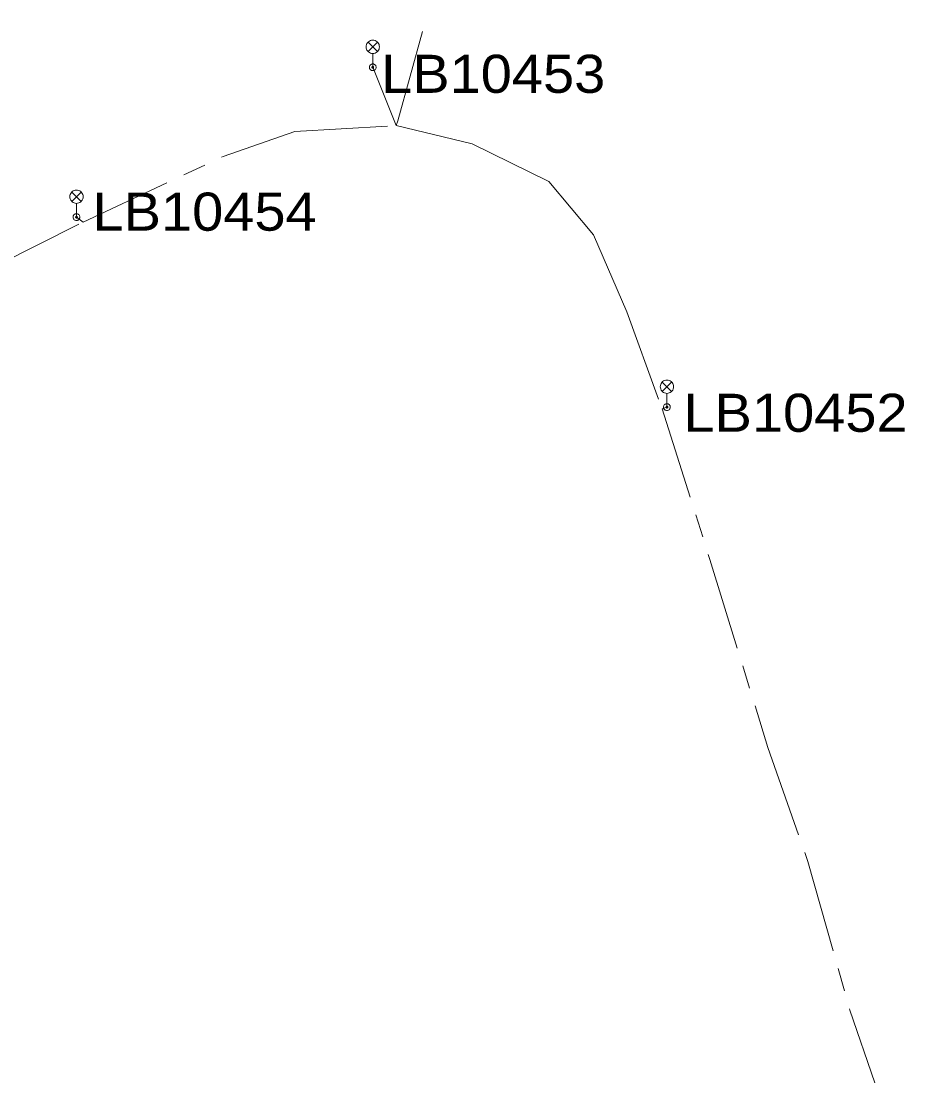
# Model space of a CAD drawing. Extents: x -691843 to -691118, y -976392 to -975793.
# Drawn here: x -691778.5 to -691728.8, y -976391.8 to -976332 of the extents above; entities that cross this region are included whole.
import ezdxf

# ---------------------------------------------------------------- set-up
doc = ezdxf.new("R2010")
doc.units = 0
doc.header["$LTSCALE"] = 0.87
doc.linetypes.add('LONG_DASH_SHORT_DASH', pattern=[9.9, 6, -1.2, 1.5, -1.2])
doc.layers.add('1', color=7, linetype='Continuous', lineweight=13)

msp = doc.modelspace()

# ---------------------------------------------------------------- linework, layer by layer
at = {"layer": '1'}
for p, q in [((-691759.005, -976333.215), (-691758.475, -976333.745)), ((-691759.005, -976333.745), (-691758.475, -976333.215)), ((-691758.74, -976334.63), (-691758.74, -976333.855)), ((-691775.695, -976341.655), (-691775.165, -976342.185)), ((-691775.695, -976342.185), (-691775.165, -976341.655)), ((-691775.43, -976343.07), (-691775.43, -976342.295)), ((-691742.435, -976352.355), (-691741.905, -976352.885)), ((-691742.435, -976352.885), (-691741.905, -976352.355)), ((-691742.17, -976353.77), (-691742.17, -976352.995))]:
    msp.add_line(p, q, dxfattribs=at)
at = {"layer": '1', "linetype": 'LONG_DASH_SHORT_DASH'}
for p, q in [((-691757.43, -976337.91), (-691758.74, -976334.63)), ((-691757.43, -976337.91), (-691758.74, -976334.63)), ((-691757.43, -976337.91), (-691758.74, -976334.63)), ((-691757.43, -976337.91), (-691758.74, -976334.63)), ((-691757.43, -976337.91), (-691758.74, -976334.63)), ((-691757.43, -976337.91), (-691758.74, -976334.63)), ((-691757.43, -976337.91), (-691758.74, -976334.63)), ((-691757.43, -976337.91), (-691758.74, -976334.63)), ((-691775.06, -976343.35), (-691775.43, -976343.07)), ((-691775.06, -976343.35), (-691775.43, -976343.07)), ((-691775.06, -976343.35), (-691775.43, -976343.07)), ((-691775.06, -976343.35), (-691775.43, -976343.07)), ((-691775.06, -976343.35), (-691775.43, -976343.07)), ((-691775.06, -976343.35), (-691775.43, -976343.07)), ((-691775.06, -976343.35), (-691775.43, -976343.07)), ((-691775.06, -976343.35), (-691775.43, -976343.07)), ((-691742.44, -976353.86), (-691742.17, -976353.77)), ((-691742.44, -976353.86), (-691742.17, -976353.77)), ((-691742.44, -976353.86), (-691742.17, -976353.77)), ((-691742.44, -976353.86), (-691742.17, -976353.77)), ((-691742.44, -976353.86), (-691742.17, -976353.77)), ((-691742.44, -976353.86), (-691742.17, -976353.77)), ((-691742.44, -976353.86), (-691742.17, -976353.77)), ((-691742.44, -976353.86), (-691742.17, -976353.77))]:
    msp.add_line(p, q, dxfattribs=at)
for points in [[(-691757.43, -976337.91), (-691757.33, -976337.64), (-691754.54, -976327.6), (-691754.53, -976324.41), (-691755.09, -976321.54), (-691752.36, -976320.81), (-691753.85, -976315.74)], [(-691757.43, -976337.91), (-691757.33, -976337.64), (-691754.54, -976327.6), (-691754.53, -976324.41), (-691755.09, -976321.54), (-691752.36, -976320.81), (-691753.85, -976315.74)], [(-691757.43, -976337.91), (-691757.33, -976337.64), (-691754.54, -976327.6), (-691754.53, -976324.41), (-691755.09, -976321.54), (-691752.36, -976320.81), (-691753.85, -976315.74)], [(-691757.43, -976337.91), (-691757.33, -976337.64), (-691754.54, -976327.6), (-691754.53, -976324.41), (-691755.09, -976321.54), (-691752.36, -976320.81), (-691753.85, -976315.74)], [(-691757.43, -976337.91), (-691757.33, -976337.64), (-691754.54, -976327.6), (-691754.53, -976324.41), (-691755.09, -976321.54), (-691752.36, -976320.81), (-691753.85, -976315.74)], [(-691757.43, -976337.91), (-691757.33, -976337.64), (-691754.54, -976327.6), (-691754.53, -976324.41), (-691755.09, -976321.54), (-691752.36, -976320.81), (-691753.85, -976315.74)], [(-691757.43, -976337.91), (-691757.33, -976337.64), (-691754.54, -976327.6), (-691754.53, -976324.41), (-691755.09, -976321.54), (-691752.36, -976320.81), (-691753.85, -976315.74)], [(-691757.43, -976337.91), (-691757.33, -976337.64), (-691754.54, -976327.6), (-691754.53, -976324.41), (-691755.09, -976321.54), (-691752.36, -976320.81), (-691753.85, -976315.74)], [(-691787.67, -976349.66), (-691775.06, -976343.35), (-691767.16, -976339.65), (-691763.13, -976338.25), (-691757.43, -976337.91)], [(-691787.67, -976349.66), (-691775.06, -976343.35), (-691767.16, -976339.65), (-691763.13, -976338.25), (-691757.43, -976337.91)], [(-691787.67, -976349.66), (-691775.06, -976343.35), (-691767.16, -976339.65), (-691763.13, -976338.25), (-691757.43, -976337.91)], [(-691787.67, -976349.66), (-691775.06, -976343.35), (-691767.16, -976339.65), (-691763.13, -976338.25), (-691757.43, -976337.91)], [(-691787.67, -976349.66), (-691775.06, -976343.35), (-691767.16, -976339.65), (-691763.13, -976338.25), (-691757.43, -976337.91)], [(-691787.67, -976349.66), (-691775.06, -976343.35), (-691767.16, -976339.65), (-691763.13, -976338.25), (-691757.43, -976337.91)], [(-691787.67, -976349.66), (-691775.06, -976343.35), (-691767.16, -976339.65), (-691763.13, -976338.25), (-691757.43, -976337.91)], [(-691787.67, -976349.66), (-691775.06, -976343.35), (-691767.16, -976339.65), (-691763.13, -976338.25), (-691757.43, -976337.91)], [(-691757.43, -976337.91), (-691753.15, -976338.95), (-691748.83, -976341.06), (-691746.31, -976344.07), (-691744.43, -976348.41), (-691742.44, -976353.86), (-691739.75, -976362.36), (-691736.48, -976372.94), (-691734.23, -976379.36), (-691731.86, -976387.73), (-691730.45, -976391.82)], [(-691757.43, -976337.91), (-691753.15, -976338.95), (-691748.83, -976341.06), (-691746.31, -976344.07), (-691744.43, -976348.41), (-691742.44, -976353.86), (-691739.75, -976362.36), (-691736.48, -976372.94), (-691734.23, -976379.36), (-691731.86, -976387.73), (-691730.45, -976391.82)], [(-691757.43, -976337.91), (-691753.15, -976338.95), (-691748.83, -976341.06), (-691746.31, -976344.07), (-691744.43, -976348.41), (-691742.44, -976353.86), (-691739.75, -976362.36), (-691736.48, -976372.94), (-691734.23, -976379.36), (-691731.86, -976387.73), (-691730.45, -976391.82)], [(-691757.43, -976337.91), (-691753.15, -976338.95), (-691748.83, -976341.06), (-691746.31, -976344.07), (-691744.43, -976348.41), (-691742.44, -976353.86), (-691739.75, -976362.36), (-691736.48, -976372.94), (-691734.23, -976379.36), (-691731.86, -976387.73), (-691730.45, -976391.82)], [(-691757.43, -976337.91), (-691753.15, -976338.95), (-691748.83, -976341.06), (-691746.31, -976344.07), (-691744.43, -976348.41), (-691742.44, -976353.86), (-691739.75, -976362.36), (-691736.48, -976372.94), (-691734.23, -976379.36), (-691731.86, -976387.73), (-691730.45, -976391.82)], [(-691757.43, -976337.91), (-691753.15, -976338.95), (-691748.83, -976341.06), (-691746.31, -976344.07), (-691744.43, -976348.41), (-691742.44, -976353.86), (-691739.75, -976362.36), (-691736.48, -976372.94), (-691734.23, -976379.36), (-691731.86, -976387.73), (-691730.45, -976391.82)], [(-691757.43, -976337.91), (-691753.15, -976338.95), (-691748.83, -976341.06), (-691746.31, -976344.07), (-691744.43, -976348.41), (-691742.44, -976353.86), (-691739.75, -976362.36), (-691736.48, -976372.94), (-691734.23, -976379.36), (-691731.86, -976387.73), (-691730.45, -976391.82)], [(-691757.43, -976337.91), (-691753.15, -976338.95), (-691748.83, -976341.06), (-691746.31, -976344.07), (-691744.43, -976348.41), (-691742.44, -976353.86), (-691739.75, -976362.36), (-691736.48, -976372.94), (-691734.23, -976379.36), (-691731.86, -976387.73), (-691730.45, -976391.82)]]:
    msp.add_lwpolyline(points, dxfattribs=at)
at = {"layer": '1'}
for points in [[(-691758.365, -976333.48), (-691758.371, -976333.415), (-691758.388, -976333.352), (-691758.415, -976333.293), (-691758.453, -976333.239), (-691758.499, -976333.193), (-691758.552, -976333.155), (-691758.612, -976333.128), (-691758.675, -976333.111), (-691758.74, -976333.105), (-691758.805, -976333.111), (-691758.868, -976333.128), (-691758.928, -976333.155), (-691758.981, -976333.193), (-691759.027, -976333.239), (-691759.065, -976333.293), (-691759.092, -976333.352), (-691759.109, -976333.415), (-691759.115, -976333.48), (-691759.109, -976333.545), (-691759.092, -976333.608), (-691759.065, -976333.668), (-691759.027, -976333.721), (-691758.981, -976333.767), (-691758.928, -976333.805), (-691758.868, -976333.832), (-691758.805, -976333.849), (-691758.74, -976333.855), (-691758.675, -976333.849), (-691758.612, -976333.832), (-691758.552, -976333.805), (-691758.499, -976333.767), (-691758.453, -976333.721), (-691758.415, -976333.668), (-691758.388, -976333.608), (-691758.371, -976333.545)], [(-691758.55, -976334.63), (-691758.553, -976334.597), (-691758.561, -976334.565), (-691758.575, -976334.535), (-691758.594, -976334.508), (-691758.618, -976334.484), (-691758.645, -976334.465), (-691758.675, -976334.451), (-691758.707, -976334.443), (-691758.74, -976334.44), (-691758.773, -976334.443), (-691758.805, -976334.451), (-691758.835, -976334.465), (-691758.862, -976334.484), (-691758.886, -976334.508), (-691758.905, -976334.535), (-691758.919, -976334.565), (-691758.927, -976334.597), (-691758.93, -976334.63), (-691758.927, -976334.663), (-691758.919, -976334.695), (-691758.905, -976334.725), (-691758.886, -976334.752), (-691758.862, -976334.776), (-691758.835, -976334.795), (-691758.805, -976334.809), (-691758.773, -976334.817), (-691758.74, -976334.82), (-691758.707, -976334.817), (-691758.675, -976334.809), (-691758.645, -976334.795), (-691758.618, -976334.776), (-691758.594, -976334.752), (-691758.575, -976334.725), (-691758.561, -976334.695), (-691758.553, -976334.663)], [(-691758.69, -976334.63), (-691758.691, -976334.621), (-691758.693, -976334.613), (-691758.697, -976334.605), (-691758.702, -976334.598), (-691758.708, -976334.592), (-691758.715, -976334.587), (-691758.723, -976334.583), (-691758.731, -976334.581), (-691758.74, -976334.58), (-691758.749, -976334.581), (-691758.757, -976334.583), (-691758.765, -976334.587), (-691758.772, -976334.592), (-691758.778, -976334.598), (-691758.783, -976334.605), (-691758.787, -976334.613), (-691758.789, -976334.621), (-691758.79, -976334.63), (-691758.789, -976334.639), (-691758.787, -976334.647), (-691758.783, -976334.655), (-691758.778, -976334.662), (-691758.772, -976334.668), (-691758.765, -976334.673), (-691758.757, -976334.677), (-691758.749, -976334.679), (-691758.74, -976334.68), (-691758.731, -976334.679), (-691758.723, -976334.677), (-691758.715, -976334.673), (-691758.708, -976334.668), (-691758.702, -976334.662), (-691758.697, -976334.655), (-691758.693, -976334.647), (-691758.691, -976334.639)], [(-691775.055, -976341.92), (-691775.061, -976341.855), (-691775.078, -976341.792), (-691775.105, -976341.732), (-691775.143, -976341.679), (-691775.189, -976341.633), (-691775.242, -976341.595), (-691775.302, -976341.568), (-691775.365, -976341.551), (-691775.43, -976341.545), (-691775.495, -976341.551), (-691775.558, -976341.568), (-691775.618, -976341.595), (-691775.671, -976341.633), (-691775.717, -976341.679), (-691775.755, -976341.732), (-691775.782, -976341.792), (-691775.799, -976341.855), (-691775.805, -976341.92), (-691775.799, -976341.985), (-691775.782, -976342.048), (-691775.755, -976342.107), (-691775.717, -976342.161), (-691775.671, -976342.207), (-691775.618, -976342.245), (-691775.558, -976342.272), (-691775.495, -976342.289), (-691775.43, -976342.295), (-691775.365, -976342.289), (-691775.302, -976342.272), (-691775.242, -976342.245), (-691775.189, -976342.207), (-691775.143, -976342.161), (-691775.105, -976342.107), (-691775.078, -976342.048), (-691775.061, -976341.985)], [(-691775.24, -976343.07), (-691775.243, -976343.037), (-691775.251, -976343.005), (-691775.265, -976342.975), (-691775.284, -976342.948), (-691775.308, -976342.924), (-691775.335, -976342.905), (-691775.365, -976342.891), (-691775.397, -976342.883), (-691775.43, -976342.88), (-691775.463, -976342.883), (-691775.495, -976342.891), (-691775.525, -976342.905), (-691775.552, -976342.924), (-691775.576, -976342.948), (-691775.595, -976342.975), (-691775.609, -976343.005), (-691775.617, -976343.037), (-691775.62, -976343.07), (-691775.617, -976343.103), (-691775.609, -976343.135), (-691775.595, -976343.165), (-691775.576, -976343.192), (-691775.552, -976343.216), (-691775.525, -976343.235), (-691775.495, -976343.249), (-691775.463, -976343.257), (-691775.43, -976343.26), (-691775.397, -976343.257), (-691775.365, -976343.249), (-691775.335, -976343.235), (-691775.308, -976343.216), (-691775.284, -976343.192), (-691775.265, -976343.165), (-691775.251, -976343.135), (-691775.243, -976343.103)], [(-691775.38, -976343.07), (-691775.381, -976343.061), (-691775.383, -976343.053), (-691775.387, -976343.045), (-691775.392, -976343.038), (-691775.398, -976343.032), (-691775.405, -976343.027), (-691775.413, -976343.023), (-691775.421, -976343.021), (-691775.43, -976343.02), (-691775.439, -976343.021), (-691775.447, -976343.023), (-691775.455, -976343.027), (-691775.462, -976343.032), (-691775.468, -976343.038), (-691775.473, -976343.045), (-691775.477, -976343.053), (-691775.479, -976343.061), (-691775.48, -976343.07), (-691775.479, -976343.079), (-691775.477, -976343.087), (-691775.473, -976343.095), (-691775.468, -976343.102), (-691775.462, -976343.108), (-691775.455, -976343.113), (-691775.447, -976343.117), (-691775.439, -976343.119), (-691775.43, -976343.12), (-691775.421, -976343.119), (-691775.413, -976343.117), (-691775.405, -976343.113), (-691775.398, -976343.108), (-691775.392, -976343.102), (-691775.387, -976343.095), (-691775.383, -976343.087), (-691775.381, -976343.079)], [(-691741.795, -976352.62), (-691741.801, -976352.555), (-691741.818, -976352.492), (-691741.845, -976352.432), (-691741.883, -976352.379), (-691741.929, -976352.333), (-691741.982, -976352.295), (-691742.042, -976352.268), (-691742.105, -976352.251), (-691742.17, -976352.245), (-691742.235, -976352.251), (-691742.298, -976352.268), (-691742.358, -976352.295), (-691742.411, -976352.333), (-691742.457, -976352.379), (-691742.495, -976352.432), (-691742.522, -976352.492), (-691742.539, -976352.555), (-691742.545, -976352.62), (-691742.539, -976352.685), (-691742.522, -976352.748), (-691742.495, -976352.808), (-691742.457, -976352.861), (-691742.411, -976352.907), (-691742.358, -976352.945), (-691742.298, -976352.972), (-691742.235, -976352.989), (-691742.17, -976352.995), (-691742.105, -976352.989), (-691742.042, -976352.972), (-691741.982, -976352.945), (-691741.929, -976352.907), (-691741.883, -976352.861), (-691741.845, -976352.808), (-691741.818, -976352.748), (-691741.801, -976352.685)], [(-691741.98, -976353.77), (-691741.983, -976353.737), (-691741.991, -976353.705), (-691742.005, -976353.675), (-691742.024, -976353.648), (-691742.048, -976353.624), (-691742.075, -976353.605), (-691742.105, -976353.591), (-691742.137, -976353.583), (-691742.17, -976353.58), (-691742.203, -976353.583), (-691742.235, -976353.591), (-691742.265, -976353.605), (-691742.292, -976353.624), (-691742.316, -976353.648), (-691742.335, -976353.675), (-691742.349, -976353.705), (-691742.357, -976353.737), (-691742.36, -976353.77), (-691742.357, -976353.803), (-691742.349, -976353.835), (-691742.335, -976353.865), (-691742.316, -976353.892), (-691742.292, -976353.916), (-691742.265, -976353.935), (-691742.235, -976353.949), (-691742.203, -976353.957), (-691742.17, -976353.96), (-691742.137, -976353.957), (-691742.105, -976353.949), (-691742.075, -976353.935), (-691742.048, -976353.916), (-691742.024, -976353.892), (-691742.005, -976353.865), (-691741.991, -976353.835), (-691741.983, -976353.803)], [(-691742.12, -976353.77), (-691742.121, -976353.761), (-691742.123, -976353.753), (-691742.127, -976353.745), (-691742.132, -976353.738), (-691742.138, -976353.732), (-691742.145, -976353.727), (-691742.153, -976353.723), (-691742.161, -976353.721), (-691742.17, -976353.72), (-691742.179, -976353.721), (-691742.187, -976353.723), (-691742.195, -976353.727), (-691742.202, -976353.732), (-691742.208, -976353.738), (-691742.213, -976353.745), (-691742.217, -976353.753), (-691742.219, -976353.761), (-691742.22, -976353.77), (-691742.219, -976353.779), (-691742.217, -976353.787), (-691742.213, -976353.795), (-691742.208, -976353.802), (-691742.202, -976353.808), (-691742.195, -976353.813), (-691742.187, -976353.817), (-691742.179, -976353.819), (-691742.17, -976353.82), (-691742.161, -976353.819), (-691742.153, -976353.817), (-691742.145, -976353.813), (-691742.138, -976353.808), (-691742.132, -976353.802), (-691742.127, -976353.795), (-691742.123, -976353.787), (-691742.121, -976353.779)]]:
    msp.add_lwpolyline(points, close=True, dxfattribs=at)

# ---------------------------------------------------------------- texts
at = {"layer": '1', "width": 1.1}
for s, p in [('LB10453', (-691758.269, -976336.07)), ('LB10454', (-691774.527, -976343.834)), ('LB10452', (-691741.24, -976355.16))]:
    msp.add_text(s, height=2.144, dxfattribs=at).set_placement(p)

doc.saveas('drawing.dxf')
